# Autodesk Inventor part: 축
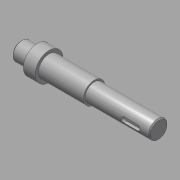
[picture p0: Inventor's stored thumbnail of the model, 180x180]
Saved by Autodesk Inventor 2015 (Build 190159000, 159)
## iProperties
Created: 2015-09
Part Number: 축
Material: 강철, 연강
Document SubType Name: Modeling
Designer: mduedu
Density: 1 g/cm^3
Appearance: 강철
Author: mduedu
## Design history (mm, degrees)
sketch "스케치1"
  geometry: L1 (-64, 0)-(64, 0); L2 (-64, 0)-(-64, 8.5); L3 (-64, 8.5)-(-49, 8.5); L4 (-49, 8.5)-(-49, 13); L5 (-49, 13)-(-38, 13); L6 (-38, 13)-(-38, 10); L7 (-38, 10)-(4, 10); L8 (4, 10)-(4, 8.5); L9 (4, 8.5)-(64, 8.5); L10 (64, 8.5)-(64, 0); 2 further points
  constraints: 20 end point, 5 parallel, 2 horizontal, 2 perpendicular, 1 coincident, 1 midpoint, 1 vertical
  dimensions: "d0" = 128 distance of L1.start L1.end; "d2" = 11 distance of L4.end L5.end; "d3" = 42 distance of L6.end L7.end; "d4" = 60 distance of L8.end L9.end; "d5" = 17 diameter of L3 L1; "d6" = 17 diameter of L9 L1; "d7" = 20 diameter of L7 L1; "d8" = 26 diameter of L5 L1
revolve "회전1" sketch "스케치1" stored, may be unused: angle "d9" = 90 deg
node "작업 평면1"
sketch "스케치2"
  geometry: L1 (5.5, 2.5)-(18.5, 2.5); L2 (18.5, -2.5)-(5.5, -2.5); L3 (5.5, 2.5)-(18.5, -2.5); L4 (18.5, 2.5)-(5.5, -2.5); L5 (30, -8.5)-(30, 8.5) reference; A1 r 2.5 centre (5.5, 0) between (5.5, 2.5) and (5.5, -2.5); A2 r 2.5 centre (18.5, 0) between (18.5, -2.5) and (18.5, 2.5); 2 further points
  constraints: 8 end point, 4 point on circle, 4 tangent, 2 centre point, 2 midpoint, 1 horizontal, 1 horizontal alignment, 1 parallel
  dimensions: "d10" = 18 dimension on A2 A1; "d12" = 9 distance edge to line of A2 L5; "d13" = 5 distance between parallel lines of L2 L1
extrude "돌출1" cut sketch "스케치2" distance "d14" = 3; taper "d15" = 0 deg
node "작업 평면2"
sketch "스케치4"
  geometry: L1 (7, -3)-(-9, -3); L2 (-9, 3)-(7, 3); L3 (-21, 10)-(-21, -10) reference; A1 r 3 centre (-9, 0) between (-9, 3) and (-9, -3); A2 r 3 centre (7, 0) between (7, -3) and (7, 3); 1 further point
  constraints: 4 end point, 4 point on circle, 4 tangent, 2 centre point, 1 horizontal, 1 horizontal alignment, 1 parallel
  dimensions: "d16" = 22 dimension on A1 A2; "d18" = 6 distance between parallel lines of L2 L1; "d19" = 9 distance edge to line of A1 L3
extrude "돌출2" cut sketch "스케치4" distance "d20" = 3.5; taper "d21" = 0 deg
sketch "스케치5"
  geometry: L1 (4, 8.5)-(64, 8.5) reference; L2 (4, -8.5)-(64, -8.5) reference; L3 (37, 8.5)-(37, -8.5); L4 (37, -6.5)-(35, -8.5); L5 (37, -8.5)-(35, -8.5); L6 (37, -8.5)-(37, -6.5); L7 (4, -10)-(4, 10) reference; 1 further point
  constraints: 8 end point, 4 point on line, 1 collinear, 1 perpendicular
  dimensions: "d22" = 4 diameter of L4.end L3; "d24" = 45 deg angle of L3 L4; "d26" = 33 distance between parallel lines of L3 L7
revolve "회전2" sketch "스케치5" stored, may be unused: angle "d27" = 90 deg
chamfer "모따기1" distance "d28" = 1; stored, may be unused: second distance "d29" = 2, angle "d30" = 45 deg
node "솔리드1"
